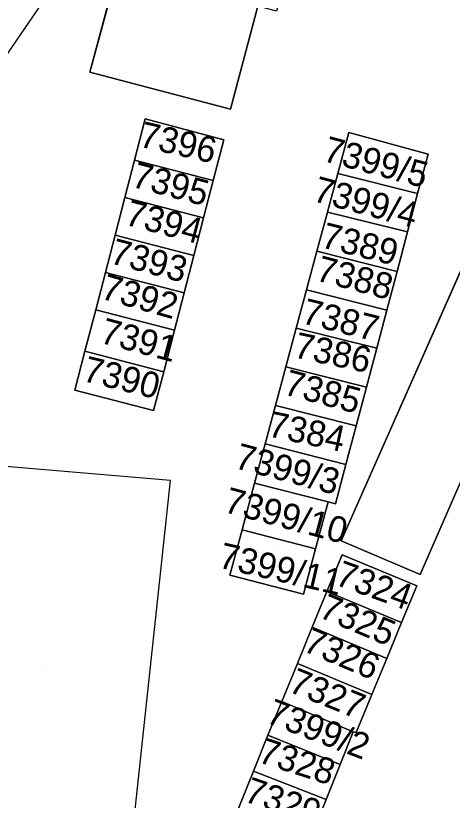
# Model space of a CAD drawing. Extents: x -266199 to -261993, y -1239047 to -1235108.
# Drawn here: x -263621.4 to -263587.6, y -1236176.6 to -1236115.8 of the extents above; entities that cross this region are included whole.
import ezdxf

# ---------------------------------------------------------------- set-up
doc = ezdxf.new("R2010")
doc.units = 0
for name, color, linetype in [('body_kn', 7, 'Continuous'), ('kladpar_druhypozemkov', 7, 'Continuous'), ('kladpar_hranice', 7, 'Continuous'), ('kladpar_parcelnecisla', 7, 'Continuous'), ('kladpar_plochy', 7, 'Continuous'), ('zappar_hrandruhpozemk', 7, 'Continuous')]:
    doc.layers.add(name, color=color, linetype=linetype)

msp = doc.modelspace()

# ---------------------------------------------------------------- linework, layer by layer
at = {"layer": 'body_kn'}
for p, q in [((-263615.66, -1236120.19), (-263615.66, -1236120.19)), ((-263604.77, -1236123.05), (-263604.77, -1236123.05)), ((-263611.39, -1236123.81), (-263611.39, -1236123.81)), ((-263611.39, -1236123.81), (-263611.39, -1236123.81)), ((-263595.61, -1236124.86), (-263595.61, -1236124.86)), ((-263595.61, -1236124.86), (-263595.61, -1236124.86)), ((-263605.29, -1236125.43), (-263605.29, -1236125.43)), ((-263589.47, -1236126.54), (-263589.47, -1236126.54)), ((-263612.22, -1236127.02), (-263612.22, -1236127.02)), ((-263596.46, -1236128.03), (-263596.46, -1236128.03)), ((-263606.11, -1236128.58), (-263606.11, -1236128.58)), ((-263606.11, -1236128.58), (-263606.11, -1236128.58)), ((-263590.28, -1236129.59), (-263590.28, -1236129.59)), ((-263590.28, -1236129.59), (-263590.28, -1236129.59)), ((-263612.97, -1236129.91), (-263612.97, -1236129.91)), ((-263606.86, -1236131.48), (-263606.86, -1236131.48)), ((-263606.86, -1236131.48), (-263606.86, -1236131.48)), ((-263597.27, -1236131.03), (-263597.27, -1236131.03)), ((-263591.07, -1236132.57), (-263591.07, -1236132.57)), ((-263591.07, -1236132.57), (-263591.07, -1236132.57)), ((-263613.72, -1236132.83), (-263613.72, -1236132.83)), ((-263607.61, -1236134.39), (-263607.61, -1236134.39)), ((-263607.61, -1236134.39), (-263607.61, -1236134.39)), ((-263598.08, -1236134.07), (-263598.08, -1236134.07)), ((-263614.47, -1236135.71), (-263614.47, -1236135.71)), ((-263591.87, -1236135.63), (-263591.87, -1236135.63)), ((-263591.87, -1236135.63), (-263591.87, -1236135.63)), ((-263608.37, -1236137.29), (-263608.37, -1236137.29)), ((-263608.37, -1236137.29), (-263608.37, -1236137.29)), ((-263598.89, -1236137.05), (-263598.89, -1236137.05)), ((-263615.22, -1236138.61), (-263615.22, -1236138.61)), ((-263592.67, -1236138.63), (-263592.67, -1236138.63)), ((-263592.67, -1236138.63), (-263592.67, -1236138.63)), ((-263599.69, -1236140.03), (-263599.69, -1236140.03)), ((-263609.12, -1236140.19), (-263609.12, -1236140.19)), ((-263609.12, -1236140.19), (-263609.12, -1236140.19)), ((-263616.05, -1236141.8), (-263616.05, -1236141.8)), ((-263593.45, -1236141.58), (-263593.45, -1236141.58)), ((-263593.45, -1236141.58), (-263593.45, -1236141.58)), ((-263600.49, -1236143.02), (-263600.49, -1236143.02)), ((-263609.95, -1236143.4), (-263609.95, -1236143.4)), ((-263609.95, -1236143.4), (-263609.95, -1236143.4)), ((-263616.83, -1236144.82), (-263616.83, -1236144.82)), ((-263594.25, -1236144.59), (-263594.25, -1236144.59)), ((-263594.25, -1236144.59), (-263594.25, -1236144.59)), ((-263601.29, -1236146.01), (-263601.29, -1236146.01)), ((-263610.73, -1236146.4), (-263610.73, -1236146.4)), ((-263595.04, -1236147.59), (-263595.04, -1236147.59)), ((-263595.04, -1236147.59), (-263595.04, -1236147.59)), ((-263602.1, -1236149), (-263602.1, -1236149)), ((-263595.83, -1236150.59), (-263595.83, -1236150.59)), ((-263595.83, -1236150.59), (-263595.83, -1236150.59)), ((-263609.42, -1236151.83), (-263609.42, -1236151.83)), ((-263602.91, -1236152.04), (-263602.91, -1236152.04)), ((-263597.22, -1236153.49), (-263597.22, -1236153.49)), ((-263597.22, -1236153.49), (-263597.22, -1236153.49)), ((-263596.64, -1236153.64), (-263596.64, -1236153.64)), ((-263603.88, -1236155.65), (-263603.88, -1236155.65)), ((-263596.21, -1236156.52), (-263596.21, -1236156.52)), ((-263598.18, -1236157.12), (-263598.18, -1236157.12)), ((-263598.18, -1236157.12), (-263598.18, -1236157.12)), ((-263596.13, -1236157.59), (-263596.13, -1236157.59)), ((-263596.13, -1236157.59), (-263596.13, -1236157.59)), ((-263604.83, -1236159.18), (-263604.83, -1236159.18)), ((-263590.08, -1236159.11), (-263590.08, -1236159.11)), ((-263590.34, -1236160), (-263590.34, -1236160)), ((-263599.12, -1236160.64), (-263599.12, -1236160.64)), ((-263597.3, -1236160.44), (-263597.3, -1236160.44)), ((-263591.52, -1236162.85), (-263591.52, -1236162.85)), ((-263591.52, -1236162.85), (-263591.52, -1236162.85)), ((-263598.44, -1236163.21), (-263598.44, -1236163.21)), ((-263592.67, -1236165.62), (-263592.67, -1236165.62)), ((-263592.67, -1236165.62), (-263592.67, -1236165.62)), ((-263599.59, -1236166.01), (-263599.59, -1236166.01)), ((-263593.83, -1236168.42), (-263593.83, -1236168.42)), ((-263593.83, -1236168.42), (-263593.83, -1236168.42)), ((-263600.81, -1236168.96), (-263600.81, -1236168.96)), ((-263601.88, -1236171.57), (-263601.88, -1236171.57)), ((-263595.26, -1236171.31), (-263595.26, -1236171.31)), ((-263595.26, -1236171.31), (-263595.26, -1236171.31)), ((-263595.05, -1236171.37), (-263595.05, -1236171.37)), ((-263596.28, -1236173.85), (-263596.28, -1236173.85)), ((-263596.28, -1236173.85), (-263596.28, -1236173.85)), ((-263603, -1236174.37), (-263603, -1236174.37)), ((-263597.37, -1236176.56), (-263597.37, -1236176.56)), ((-263597.37, -1236176.56), (-263597.37, -1236176.56))]:
    msp.add_line(p, q, dxfattribs=at)
at = {"layer": 'kladpar_druhypozemkov'}
for p, q in [((-263608.44, -1236125.07), (-263608.44, -1236125.07)), ((-263592.34, -1236126.15), (-263592.34, -1236126.15)), ((-263609.27, -1236128.27), (-263609.27, -1236128.27)), ((-263593.22, -1236129.38), (-263593.22, -1236129.38)), ((-263610, -1236131.1), (-263610, -1236131.1)), ((-263594.1, -1236132.43), (-263594.1, -1236132.43)), ((-263610.66, -1236134.12), (-263610.66, -1236134.12)), ((-263594.87, -1236135.51), (-263594.87, -1236135.51)), ((-263611.42, -1236137.07), (-263611.42, -1236137.07)), ((-263595.78, -1236138.3), (-263595.78, -1236138.3)), ((-263612.18, -1236140.05), (-263612.18, -1236140.05)), ((-263596.66, -1236141.3), (-263596.66, -1236141.3)), ((-263613.04, -1236143.2), (-263613.04, -1236143.2)), ((-263597.32, -1236144.31), (-263597.32, -1236144.31)), ((-263598.35, -1236147.28), (-263598.35, -1236147.28)), ((-263599.16, -1236150.11), (-263599.16, -1236150.11)), ((-263600.07, -1236153.3), (-263600.07, -1236153.3)), ((-263601.21, -1236156.9), (-263601.21, -1236156.9)), ((-263593.17, -1236159.35), (-263593.17, -1236159.35)), ((-263594.13, -1236162.43), (-263594.13, -1236162.43)), ((-263595.5, -1236165.14), (-263595.5, -1236165.14)), ((-263619, -1236166.26), (-263619, -1236166.26)), ((-263596.56, -1236168.12), (-263596.56, -1236168.12)), ((-263598.32, -1236170.58), (-263598.32, -1236170.58)), ((-263599.69, -1236173.11), (-263599.69, -1236173.11)), ((-263600.65, -1236176.14), (-263600.65, -1236176.14))]:
    msp.add_line(p, q, dxfattribs=at)
at = {"layer": 'kladpar_hranice'}
for points in [[(-263599.94, -1236104.89), (-263602.06, -1236112.85), (-263600.59, -1236113.22), (-263601.22, -1236115.46), (-263602.65, -1236115.08), (-263604.77, -1236123.05), (-263615.66, -1236120.19), (-263613.44, -1236111.9), (-263613.99, -1236111.81), (-263613.57, -1236110.19), (-263613.03, -1236110.36), (-263610.8, -1236102.02), (-263610.47, -1236102.11), (-263599.94, -1236104.89)], [(-263613.44, -1236111.9), (-263615.66, -1236120.19), (-263604.77, -1236123.05), (-263602.65, -1236115.08)], [(-263578.88, -1236117.35), (-263572.88, -1236119.83), (-263579.03, -1236133.87), (-263576.91, -1236134.74), (-263578.26, -1236137.85), (-263580.38, -1236136.88), (-263590.08, -1236159.11), (-263596.21, -1236156.52), (-263578.88, -1236117.35)], [(-263572.88, -1236119.83), (-263578.88, -1236117.35), (-263596.21, -1236156.52), (-263590.08, -1236159.11), (-263580.38, -1236136.88), (-263578.26, -1236137.85), (-263576.91, -1236134.74), (-263579.03, -1236133.87), (-263572.88, -1236119.83)], [(-263610.73, -1236146.4), (-263609.95, -1236143.4), (-263609.12, -1236140.19), (-263608.37, -1236137.29), (-263607.61, -1236134.39), (-263606.86, -1236131.48), (-263606.11, -1236128.58), (-263605.29, -1236125.43), (-263611.39, -1236123.81), (-263612.22, -1236127.02), (-263612.97, -1236129.91), (-263613.72, -1236132.83), (-263614.47, -1236135.71), (-263615.22, -1236138.61), (-263616.05, -1236141.8), (-263616.83, -1236144.82), (-263610.73, -1236146.4)], [(-263611.39, -1236123.81), (-263605.29, -1236125.43), (-263606.11, -1236128.58), (-263612.22, -1236127.02), (-263611.39, -1236123.81)], [(-263599.12, -1236160.64), (-263598.18, -1236157.12), (-263597.22, -1236153.49), (-263596.64, -1236153.64), (-263595.83, -1236150.59), (-263595.04, -1236147.59), (-263594.25, -1236144.59), (-263593.45, -1236141.58), (-263592.67, -1236138.63), (-263591.87, -1236135.63), (-263591.07, -1236132.57), (-263590.28, -1236129.59), (-263589.47, -1236126.54), (-263595.61, -1236124.86), (-263596.46, -1236128.03), (-263597.27, -1236131.03), (-263598.08, -1236134.07), (-263598.89, -1236137.05), (-263599.69, -1236140.03), (-263600.49, -1236143.02), (-263601.29, -1236146.01), (-263602.1, -1236149), (-263602.91, -1236152.04), (-263603.88, -1236155.65), (-263604.83, -1236159.18), (-263599.12, -1236160.64)], [(-263595.61, -1236124.86), (-263589.47, -1236126.54), (-263590.28, -1236129.59), (-263596.46, -1236128.03), (-263595.61, -1236124.86)], [(-263606.11, -1236128.58), (-263606.86, -1236131.48), (-263612.97, -1236129.91), (-263612.22, -1236127.02), (-263606.11, -1236128.58)], [(-263590.28, -1236129.59), (-263591.07, -1236132.57), (-263597.27, -1236131.03), (-263596.46, -1236128.03), (-263590.28, -1236129.59)], [(-263606.86, -1236131.48), (-263607.61, -1236134.39), (-263613.72, -1236132.83), (-263612.97, -1236129.91), (-263606.86, -1236131.48)], [(-263591.07, -1236132.57), (-263591.87, -1236135.63), (-263598.08, -1236134.07), (-263597.27, -1236131.03), (-263591.07, -1236132.57)], [(-263607.61, -1236134.39), (-263608.37, -1236137.29), (-263614.47, -1236135.71), (-263613.72, -1236132.83), (-263607.61, -1236134.39)], [(-263591.87, -1236135.63), (-263592.67, -1236138.63), (-263598.89, -1236137.05), (-263598.08, -1236134.07), (-263591.87, -1236135.63)], [(-263608.37, -1236137.29), (-263609.12, -1236140.19), (-263615.22, -1236138.61), (-263614.47, -1236135.71), (-263608.37, -1236137.29)], [(-263592.67, -1236138.63), (-263593.45, -1236141.58), (-263599.69, -1236140.03), (-263598.89, -1236137.05), (-263592.67, -1236138.63)], [(-263609.12, -1236140.19), (-263609.95, -1236143.4), (-263616.05, -1236141.8), (-263615.22, -1236138.61), (-263609.12, -1236140.19)], [(-263593.45, -1236141.58), (-263594.25, -1236144.59), (-263600.49, -1236143.02), (-263599.69, -1236140.03), (-263593.45, -1236141.58)], [(-263609.95, -1236143.4), (-263610.73, -1236146.4), (-263616.83, -1236144.82), (-263616.05, -1236141.8), (-263609.95, -1236143.4)], [(-263594.25, -1236144.59), (-263595.04, -1236147.59), (-263601.29, -1236146.01), (-263600.49, -1236143.02), (-263594.25, -1236144.59)], [(-263595.04, -1236147.59), (-263595.83, -1236150.59), (-263602.1, -1236149), (-263601.29, -1236146.01), (-263595.04, -1236147.59)], [(-263595.83, -1236150.59), (-263596.64, -1236153.64), (-263597.22, -1236153.49), (-263602.91, -1236152.04), (-263602.1, -1236149), (-263595.83, -1236150.59)], [(-263597.22, -1236153.49), (-263598.18, -1236157.12), (-263603.88, -1236155.65), (-263602.91, -1236152.04), (-263597.22, -1236153.49)], [(-263598.18, -1236157.12), (-263599.12, -1236160.64), (-263604.83, -1236159.18), (-263603.88, -1236155.65), (-263598.18, -1236157.12)], [(-263598.6, -1236179.62), (-263597.37, -1236176.56), (-263596.28, -1236173.85), (-263595.26, -1236171.31), (-263595.05, -1236171.37), (-263593.83, -1236168.42), (-263592.67, -1236165.62), (-263591.52, -1236162.85), (-263590.34, -1236160), (-263596.13, -1236157.59), (-263597.3, -1236160.44), (-263598.44, -1236163.21), (-263599.59, -1236166.01), (-263600.81, -1236168.96), (-263601.88, -1236171.57), (-263603, -1236174.37), (-263604.24, -1236177.43)], [(-263596.13, -1236157.59), (-263590.34, -1236160), (-263591.52, -1236162.85), (-263597.3, -1236160.44), (-263596.13, -1236157.59)], [(-263591.52, -1236162.85), (-263592.67, -1236165.62), (-263598.44, -1236163.21), (-263597.3, -1236160.44), (-263591.52, -1236162.85)], [(-263592.67, -1236165.62), (-263593.83, -1236168.42), (-263599.59, -1236166.01), (-263598.44, -1236163.21), (-263592.67, -1236165.62)], [(-263593.83, -1236168.42), (-263595.05, -1236171.37), (-263595.26, -1236171.31), (-263600.81, -1236168.96), (-263599.59, -1236166.01), (-263593.83, -1236168.42)], [(-263595.26, -1236171.31), (-263596.28, -1236173.85), (-263601.88, -1236171.57), (-263600.81, -1236168.96), (-263595.26, -1236171.31)], [(-263596.28, -1236173.85), (-263597.37, -1236176.56), (-263603, -1236174.37), (-263601.88, -1236171.57), (-263596.28, -1236173.85)], [(-263597.37, -1236176.56), (-263598.6, -1236179.62), (-263604.24, -1236177.43), (-263603, -1236174.37), (-263597.37, -1236176.56)]]:
    msp.add_lwpolyline(points, dxfattribs=at)
at = {"layer": 'kladpar_plochy'}
for p, q in [((-263613.44, -1236111.9), (-263615.66, -1236120.19)), ((-263604.77, -1236123.05), (-263602.65, -1236115.08)), ((-263578.88, -1236117.35), (-263596.21, -1236156.52)), ((-263615.66, -1236120.19), (-263604.77, -1236123.05)), ((-263611.39, -1236123.81), (-263612.22, -1236127.02)), ((-263605.29, -1236125.43), (-263611.39, -1236123.81)), ((-263595.61, -1236124.86), (-263596.46, -1236128.03)), ((-263589.47, -1236126.54), (-263595.61, -1236124.86)), ((-263606.11, -1236128.58), (-263605.29, -1236125.43)), ((-263590.28, -1236129.59), (-263589.47, -1236126.54)), ((-263612.22, -1236127.02), (-263612.97, -1236129.91)), ((-263596.46, -1236128.03), (-263597.27, -1236131.03)), ((-263606.86, -1236131.48), (-263606.11, -1236128.58)), ((-263591.07, -1236132.57), (-263590.28, -1236129.59)), ((-263612.97, -1236129.91), (-263613.72, -1236132.83)), ((-263607.61, -1236134.39), (-263606.86, -1236131.48)), ((-263597.27, -1236131.03), (-263598.08, -1236134.07)), ((-263591.87, -1236135.63), (-263591.07, -1236132.57)), ((-263613.72, -1236132.83), (-263614.47, -1236135.71)), ((-263608.37, -1236137.29), (-263607.61, -1236134.39)), ((-263598.08, -1236134.07), (-263598.89, -1236137.05)), ((-263614.47, -1236135.71), (-263615.22, -1236138.61)), ((-263592.67, -1236138.63), (-263591.87, -1236135.63)), ((-263590.08, -1236159.11), (-263580.38, -1236136.88)), ((-263609.12, -1236140.19), (-263608.37, -1236137.29)), ((-263598.89, -1236137.05), (-263599.69, -1236140.03)), ((-263615.22, -1236138.61), (-263616.05, -1236141.8)), ((-263593.45, -1236141.58), (-263592.67, -1236138.63)), ((-263599.69, -1236140.03), (-263600.49, -1236143.02)), ((-263609.95, -1236143.4), (-263609.12, -1236140.19)), ((-263616.05, -1236141.8), (-263616.83, -1236144.82)), ((-263594.25, -1236144.59), (-263593.45, -1236141.58)), ((-263600.49, -1236143.02), (-263601.29, -1236146.01)), ((-263610.73, -1236146.4), (-263609.95, -1236143.4)), ((-263616.83, -1236144.82), (-263610.73, -1236146.4)), ((-263595.04, -1236147.59), (-263594.25, -1236144.59)), ((-263601.29, -1236146.01), (-263602.1, -1236149)), ((-263595.83, -1236150.59), (-263595.04, -1236147.59)), ((-263602.1, -1236149), (-263602.91, -1236152.04)), ((-263596.64, -1236153.64), (-263595.83, -1236150.59)), ((-263602.91, -1236152.04), (-263603.88, -1236155.65)), ((-263598.18, -1236157.12), (-263597.22, -1236153.49)), ((-263597.22, -1236153.49), (-263596.64, -1236153.64)), ((-263603.88, -1236155.65), (-263604.83, -1236159.18)), ((-263596.21, -1236156.52), (-263590.08, -1236159.11)), ((-263599.12, -1236160.64), (-263598.18, -1236157.12)), ((-263596.13, -1236157.59), (-263597.3, -1236160.44)), ((-263590.34, -1236160), (-263596.13, -1236157.59)), ((-263604.83, -1236159.18), (-263599.12, -1236160.64)), ((-263591.52, -1236162.85), (-263590.34, -1236160)), ((-263597.3, -1236160.44), (-263598.44, -1236163.21)), ((-263592.67, -1236165.62), (-263591.52, -1236162.85)), ((-263598.44, -1236163.21), (-263599.59, -1236166.01)), ((-263593.83, -1236168.42), (-263592.67, -1236165.62)), ((-263599.59, -1236166.01), (-263600.81, -1236168.96)), ((-263595.05, -1236171.37), (-263593.83, -1236168.42)), ((-263600.81, -1236168.96), (-263601.88, -1236171.57)), ((-263601.88, -1236171.57), (-263603, -1236174.37)), ((-263596.28, -1236173.85), (-263595.26, -1236171.31)), ((-263595.26, -1236171.31), (-263595.05, -1236171.37)), ((-263597.37, -1236176.56), (-263596.28, -1236173.85)), ((-263603, -1236174.37), (-263604.24, -1236177.43)), ((-263598.6, -1236179.62), (-263597.37, -1236176.56))]:
    msp.add_line(p, q, dxfattribs=at)
for points in [[(-263599.94, -1236104.89), (-263602.06, -1236112.85), (-263600.59, -1236113.22), (-263601.22, -1236115.46), (-263602.65, -1236115.08), (-263604.77, -1236123.05), (-263615.66, -1236120.19), (-263613.44, -1236111.9), (-263613.99, -1236111.81), (-263613.57, -1236110.19), (-263613.03, -1236110.36), (-263610.8, -1236102.02), (-263610.47, -1236102.11)], [(-263578.88, -1236117.35), (-263572.88, -1236119.83), (-263579.03, -1236133.87), (-263576.91, -1236134.74), (-263578.26, -1236137.85), (-263580.38, -1236136.88), (-263590.08, -1236159.11), (-263596.21, -1236156.52)], [(-263611.39, -1236123.81), (-263605.29, -1236125.43), (-263606.11, -1236128.58), (-263612.22, -1236127.02)], [(-263595.61, -1236124.86), (-263589.47, -1236126.54), (-263590.28, -1236129.59), (-263596.46, -1236128.03)], [(-263606.11, -1236128.58), (-263606.86, -1236131.48), (-263612.97, -1236129.91), (-263612.22, -1236127.02)], [(-263590.28, -1236129.59), (-263591.07, -1236132.57), (-263597.27, -1236131.03), (-263596.46, -1236128.03)], [(-263606.86, -1236131.48), (-263607.61, -1236134.39), (-263613.72, -1236132.83), (-263612.97, -1236129.91)], [(-263591.07, -1236132.57), (-263591.87, -1236135.63), (-263598.08, -1236134.07), (-263597.27, -1236131.03)], [(-263607.61, -1236134.39), (-263608.37, -1236137.29), (-263614.47, -1236135.71), (-263613.72, -1236132.83)], [(-263591.87, -1236135.63), (-263592.67, -1236138.63), (-263598.89, -1236137.05), (-263598.08, -1236134.07)], [(-263608.37, -1236137.29), (-263609.12, -1236140.19), (-263615.22, -1236138.61), (-263614.47, -1236135.71)], [(-263592.67, -1236138.63), (-263593.45, -1236141.58), (-263599.69, -1236140.03), (-263598.89, -1236137.05)], [(-263609.12, -1236140.19), (-263609.95, -1236143.4), (-263616.05, -1236141.8), (-263615.22, -1236138.61)], [(-263593.45, -1236141.58), (-263594.25, -1236144.59), (-263600.49, -1236143.02), (-263599.69, -1236140.03)], [(-263609.95, -1236143.4), (-263610.73, -1236146.4), (-263616.83, -1236144.82), (-263616.05, -1236141.8)], [(-263594.25, -1236144.59), (-263595.04, -1236147.59), (-263601.29, -1236146.01), (-263600.49, -1236143.02)], [(-263595.04, -1236147.59), (-263595.83, -1236150.59), (-263602.1, -1236149), (-263601.29, -1236146.01)], [(-263595.83, -1236150.59), (-263596.64, -1236153.64), (-263597.22, -1236153.49), (-263602.91, -1236152.04), (-263602.1, -1236149)], [(-263597.22, -1236153.49), (-263598.18, -1236157.12), (-263603.88, -1236155.65), (-263602.91, -1236152.04)], [(-263598.18, -1236157.12), (-263599.12, -1236160.64), (-263604.83, -1236159.18), (-263603.88, -1236155.65)], [(-263596.13, -1236157.59), (-263590.34, -1236160), (-263591.52, -1236162.85), (-263597.3, -1236160.44)], [(-263591.52, -1236162.85), (-263592.67, -1236165.62), (-263598.44, -1236163.21), (-263597.3, -1236160.44)], [(-263592.67, -1236165.62), (-263593.83, -1236168.42), (-263599.59, -1236166.01), (-263598.44, -1236163.21)], [(-263593.83, -1236168.42), (-263595.05, -1236171.37), (-263595.26, -1236171.31), (-263600.81, -1236168.96), (-263599.59, -1236166.01)], [(-263595.26, -1236171.31), (-263596.28, -1236173.85), (-263601.88, -1236171.57), (-263600.81, -1236168.96)], [(-263596.28, -1236173.85), (-263597.37, -1236176.56), (-263603, -1236174.37), (-263601.88, -1236171.57)], [(-263597.37, -1236176.56), (-263598.6, -1236179.62), (-263604.24, -1236177.43), (-263603, -1236174.37)]]:
    msp.add_lwpolyline(points, close=True, dxfattribs=at)
at = {"layer": 'zappar_hrandruhpozemk'}
msp.add_line((-263612.6, -1236181.54), (-263609.42, -1236151.83), dxfattribs=at)
for points in [[(-263618.36, -1236110.66), (-263616.82, -1236111.04), (-263628.89, -1236128.68)], [(-263609.42, -1236151.83), (-263624.35, -1236150.57), (-263627.14, -1236179.91)]]:
    msp.add_lwpolyline(points, dxfattribs=at)

# ---------------------------------------------------------------- texts
at = {"layer": 'kladpar_parcelnecisla'}
for s, rotation, p in [('7396', 347, (-263611.939, -1236125.932)), ('7399/5', 345, (-263597.71, -1236127.052)), ('7395', 345, (-263612.539, -1236129.042)), ('7399/4', 345, (-263598.487, -1236130.156)), ('7394', 345, (-263613.056, -1236131.977)), ('7389', 346, (-263597.864, -1236133.747)), ('7393', 345, (-263614.205, -1236134.97)), ('7388', 345, (-263598.269, -1236136.302)), ('7392', 344, (-263614.921, -1236137.705)), ('7387', 346, (-263599.358, -1236139.628)), ('7391', 345, (-263614.981, -1236141.133)), ('7386', 348, (-263599.965, -1236142.274)), ('7390', 346, (-263616.324, -1236144.097)), ('7385', 345, (-263600.76, -1236145.134)), ('7384', 348, (-263601.965, -1236148.394)), ('7399/3', 345, (-263604.556, -1236150.84)), ('7399/10', 345, (-263605.385, -1236154.254)), ('7399/11', 347, (-263605.797, -1236158.563)), ('7324', 340, (-263596.778, -1236159.868)), ('7325', 337, (-263598.035, -1236162.378)), ('7326', 337, (-263599.264, -1236165)), ('7327', 338, (-263600.386, -1236168.157)), ('7399/2', 339, (-263602.129, -1236170.565)), ('7328', 342, (-263602.744, -1236173.629)), ('7329', 341, (-263603.83, -1236176.667))]:
    msp.add_text(s, height=2, rotation=rotation, dxfattribs=at).set_placement(p)

doc.saveas('drawing.dxf')
